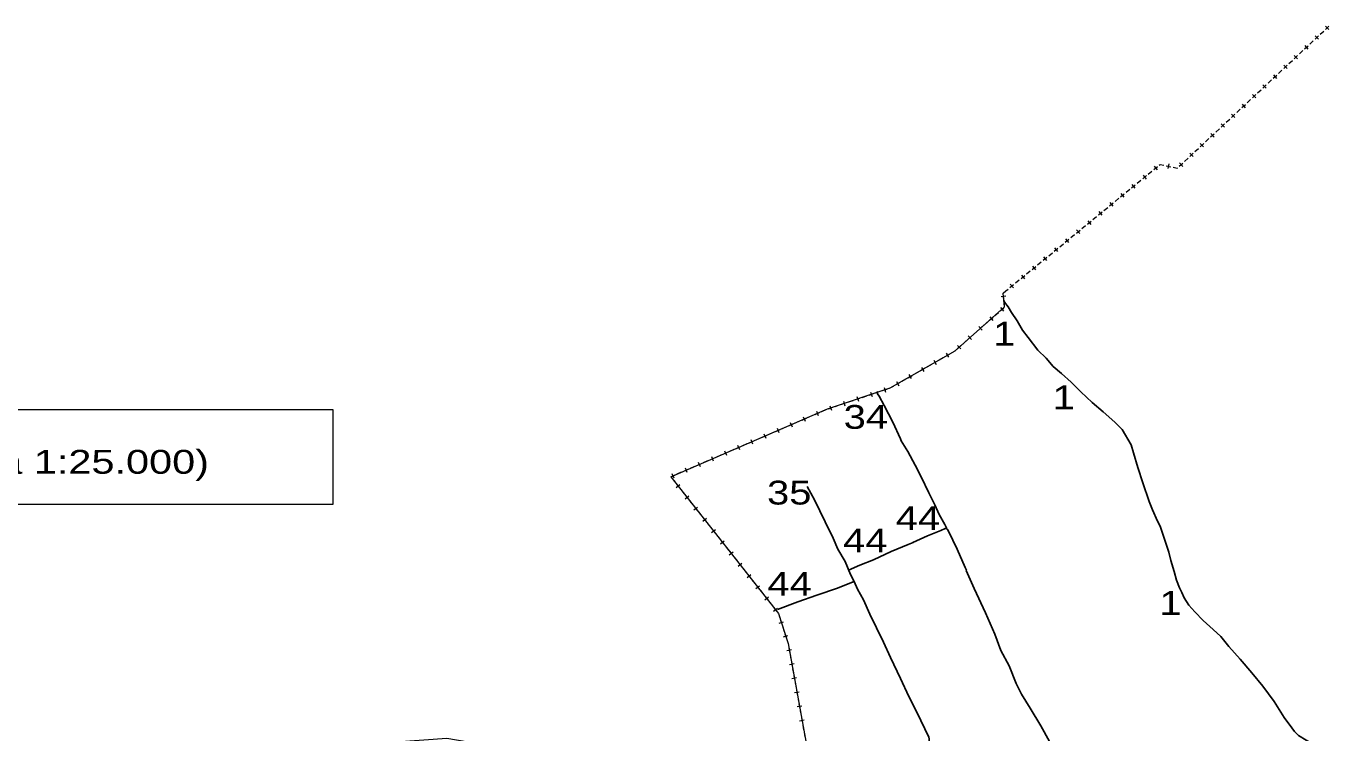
# Model space of a CAD drawing. Extents: x 476989 to 498418, y 4381813 to 4416555.
# Drawn here: x 483391 to 486122, y 4387830 to 4389313 of the extents above; entities that cross this region are included whole.
import ezdxf
from ezdxf.enums import TextEntityAlignment as Align

# ---------------------------------------------------------------- set-up
doc = ezdxf.new("R2010")
doc.units = 0
doc.header["$LTSCALE"] = 20
for name, color, linetype, lineweight in [('13', 7, 'Continuous', 13), ('34', 7, 'Continuous', 13), ('6', 7, 'Continuous', 25)]:
    doc.layers.add(name, color=color, linetype=linetype, lineweight=lineweight)

msp = doc.modelspace()

# ---------------------------------------------------------------- linework, layer by layer
at = {"layer": '13'}
msp.add_lwpolyline([(480316.85, 4388508.69), (484033.85, 4388508.69), (484033.85, 4388309.52), (480316.85, 4388309.52)], close=True, dxfattribs=at)
at = {"layer": '34'}
for p, q in [((486103.63, 4389295.79), (486110.92, 4389302.62)), ((486114.56, 4389306.04), (486121.86, 4389312.87)), ((486114.79, 4389313.1), (486121.63, 4389305.81)), ((486081.74, 4389275.28), (486089.04, 4389282.12)), ((486092.68, 4389285.53), (486099.98, 4389292.37)), ((486092.91, 4389292.6), (486099.75, 4389285.3)), ((486048.91, 4389244.52), (486056.21, 4389251.35)), ((486049.14, 4389251.58), (486055.98, 4389244.29)), ((486059.86, 4389254.77), (486067.16, 4389261.61)), ((486070.8, 4389265.02), (486078.09, 4389271.86)), ((486071.03, 4389272.09), (486077.86, 4389264.79)), ((486016.09, 4389213.76), (486023.39, 4389220.6)), ((486027.03, 4389224.01), (486034.33, 4389230.85)), ((486027.26, 4389231.08), (486034.1, 4389223.78)), ((486037.98, 4389234.27), (486045.27, 4389241.1)), ((485994.21, 4389193.25), (486001.51, 4389200.09)), ((486005.15, 4389203.5), (486012.45, 4389210.34)), ((486005.38, 4389210.57), (486012.22, 4389203.27)), ((485961.38, 4389162.49), (485968.68, 4389169.33)), ((485961.61, 4389169.55), (485968.45, 4389162.26)), ((485972.33, 4389172.74), (485979.62, 4389179.58)), ((485983.27, 4389182.99), (485990.56, 4389189.83)), ((485983.5, 4389190.06), (485990.33, 4389182.77)), ((485928.56, 4389131.73), (485935.86, 4389138.57)), ((485939.5, 4389141.98), (485946.8, 4389148.82)), ((485939.73, 4389149.05), (485946.57, 4389141.75)), ((485950.45, 4389152.24), (485957.74, 4389159.08)), ((485906.68, 4389111.22), (485913.98, 4389118.06)), ((485917.62, 4389121.47), (485924.91, 4389128.31)), ((485917.85, 4389128.54), (485924.68, 4389121.24)), ((485873.85, 4389080.46), (485881.15, 4389087.3)), ((485874.08, 4389087.53), (485880.92, 4389080.23)), ((485884.8, 4389090.72), (485892.09, 4389097.55)), ((485895.73, 4389100.97), (485903.03, 4389107.8)), ((485895.96, 4389108.03), (485902.8, 4389100.74)), ((485841.03, 4389049.7), (485848.33, 4389056.54)), ((485851.97, 4389059.95), (485859.27, 4389066.79)), ((485852.2, 4389067.02), (485859.04, 4389059.72)), ((485862.91, 4389070.21), (485870.21, 4389077.05)), ((485819.15, 4389029.2), (485826.44, 4389036.03)), ((485830.09, 4389039.45), (485837.38, 4389046.28)), ((485830.31, 4389046.51), (485837.15, 4389039.22)), ((485743.01, 4389002.49), (485750.74, 4389008.83)), ((485754.59, 4389012), (485762.32, 4389018.34)), ((485755.29, 4389019.04), (485761.63, 4389011.31)), ((485780.35, 4389020.26), (485790.11, 4389018.09)), ((485786.31, 4389024.05), (485784.14, 4389014.29)), ((485808.2, 4389018.94), (485815.5, 4389025.78)), ((485808.43, 4389026.01), (485815.27, 4389018.71)), ((485708.23, 4388973.95), (485715.96, 4388980.29)), ((485708.92, 4388980.98), (485715.27, 4388973.25)), ((485719.82, 4388983.46), (485727.55, 4388989.81)), ((485731.41, 4388992.97), (485739.14, 4388999.32)), ((485732.1, 4389000.01), (485738.45, 4388992.28)), ((485673.46, 4388945.41), (485681.19, 4388951.76)), ((485685.05, 4388954.92), (485692.78, 4388961.27)), ((485685.74, 4388961.96), (485692.08, 4388954.23)), ((485696.64, 4388964.44), (485704.37, 4388970.78)), ((485638.68, 4388916.87), (485646.41, 4388923.22)), ((485639.37, 4388923.91), (485645.72, 4388916.18)), ((485650.28, 4388926.39), (485658.01, 4388932.73)), ((485661.86, 4388935.9), (485669.59, 4388942.24)), ((485662.56, 4388942.93), (485668.9, 4388935.2)), ((485603.91, 4388888.34), (485611.64, 4388894.68)), ((485615.5, 4388897.85), (485623.23, 4388904.19)), ((485616.19, 4388904.88), (485622.54, 4388897.15)), ((485627.09, 4388907.36), (485634.82, 4388913.71)), ((485569.13, 4388859.8), (485576.86, 4388866.14)), ((485569.83, 4388866.83), (485576.17, 4388859.1)), ((485580.73, 4388869.31), (485588.46, 4388875.66)), ((485592.32, 4388878.82), (485600.05, 4388885.16)), ((485593.01, 4388885.86), (485599.35, 4388878.13)), ((485534.36, 4388831.26), (485542.09, 4388837.6)), ((485545.95, 4388840.77), (485553.68, 4388847.11)), ((485546.64, 4388847.81), (485552.99, 4388840.08)), ((485557.55, 4388850.29), (485565.28, 4388856.63)), ((485499.58, 4388802.72), (485507.31, 4388809.06)), ((485500.28, 4388809.76), (485506.62, 4388802.03)), ((485511.18, 4388812.24), (485518.91, 4388818.58)), ((485522.77, 4388821.75), (485530.5, 4388828.09)), ((485523.46, 4388828.78), (485529.8, 4388821.05)), ((485476.4, 4388783.69), (485484.13, 4388790.04)), ((485477.09, 4388790.73), (485483.44, 4388783)), ((485488, 4388793.21), (485495.73, 4388799.55)), ((485441.63, 4388755.16), (485444.8, 4388757.76)), ((485444.8, 4388757.76), (485449.36, 4388761.5)), ((485453.22, 4388764.67), (485460.95, 4388771.01)), ((485453.91, 4388771.71), (485460.26, 4388763.98)), ((485464.81, 4388774.19), (485472.54, 4388780.53)), ((485434.71, 4388745.92), (485444.65, 4388746.95)), ((485440.19, 4388741.47), (485439.16, 4388751.41)), ((485441.74, 4388726.56), (485440.71, 4388736.5)), ((485410.23, 4388695.89), (485417.72, 4388702.52)), ((485410.66, 4388702.95), (485417.28, 4388695.46)), ((485421.46, 4388705.83), (485428.95, 4388712.46)), ((485432.69, 4388715.76), (485440.18, 4388722.39)), ((485433.12, 4388722.82), (485439.75, 4388715.33)), ((485376.54, 4388666.09), (485384.03, 4388672.72)), ((485387.76, 4388676.02), (485395.25, 4388682.65)), ((485388.2, 4388683.08), (485394.82, 4388675.59)), ((485399, 4388685.96), (485406.49, 4388692.59)), ((485354.07, 4388646.22), (485361.56, 4388652.85)), ((485365.3, 4388656.15), (485372.79, 4388662.78)), ((485365.73, 4388663.21), (485372.36, 4388655.72)), ((485304.59, 4388612.84), (485313.26, 4388617.81)), ((485317.59, 4388620.29), (485326.26, 4388625.27)), ((485319.44, 4388627.12), (485324.41, 4388618.44)), ((485342.84, 4388636.28), (485350.33, 4388642.91)), ((485343.27, 4388643.34), (485349.9, 4388635.85)), ((485265.56, 4388590.45), (485274.23, 4388595.43)), ((485267.41, 4388597.28), (485272.38, 4388588.6)), ((485278.57, 4388597.92), (485287.25, 4388602.89)), ((485291.58, 4388605.37), (485300.25, 4388610.35)), ((485293.42, 4388612.2), (485298.4, 4388603.52)), ((485213.53, 4388560.61), (485222.2, 4388565.59)), ((485215.38, 4388567.44), (485220.35, 4388558.76)), ((485226.54, 4388568.08), (485235.22, 4388573.05)), ((485239.54, 4388575.53), (485248.22, 4388580.51)), ((485241.39, 4388582.36), (485246.37, 4388573.68)), ((485252.56, 4388583), (485261.23, 4388587.97)), ((485132.46, 4388535.92), (485135.64, 4388526.44)), ((485143.53, 4388534.36), (485153.01, 4388537.55)), ((485157.74, 4388539.13), (485167.22, 4388542.32)), ((485160.89, 4388545.47), (485164.07, 4388535.99)), ((485171.96, 4388543.91), (485181.44, 4388547.09)), ((485186.17, 4388548.68), (485195.65, 4388551.87)), ((485189.32, 4388555.02), (485192.5, 4388545.54)), ((485058.65, 4388504.67), (485067.83, 4388508.63)), ((485072.45, 4388510.49), (485081.93, 4388513.67)), ((485075.6, 4388516.82), (485078.79, 4388507.34)), ((485086.67, 4388515.26), (485096.15, 4388518.45)), ((485100.88, 4388520.04), (485110.36, 4388523.22)), ((485104.03, 4388526.37), (485107.21, 4388516.89)), ((485115.1, 4388524.81), (485124.58, 4388528)), ((485129.31, 4388529.59), (485138.79, 4388532.77)), ((484992.41, 4388481.53), (484996.38, 4388472.35)), ((485003.58, 4388480.9), (485012.76, 4388484.86)), ((485017.34, 4388486.84), (485026.52, 4388490.8)), ((485019.95, 4388493.41), (485023.91, 4388484.23)), ((485031.11, 4388492.78), (485040.29, 4388496.75)), ((485044.87, 4388498.72), (485054.05, 4388502.69)), ((485047.48, 4388505.3), (485051.45, 4388496.11)), ((484934.73, 4388451.19), (484943.92, 4388455.15)), ((484937.34, 4388457.76), (484941.31, 4388448.58)), ((484948.51, 4388457.13), (484957.69, 4388461.09)), ((484962.27, 4388463.07), (484971.45, 4388467.03)), ((484964.88, 4388469.64), (484968.84, 4388460.46)), ((484976.04, 4388469.01), (484985.22, 4388472.98)), ((484989.8, 4388474.95), (484998.99, 4388478.92)), ((484879.66, 4388427.42), (484888.85, 4388431.38)), ((484882.27, 4388433.99), (484886.24, 4388424.81)), ((484893.44, 4388433.36), (484902.62, 4388437.32)), ((484907.2, 4388439.3), (484916.38, 4388443.26)), ((484909.81, 4388445.87), (484913.77, 4388436.69)), ((484920.97, 4388445.25), (484930.15, 4388449.21)), ((484810.83, 4388397.71), (484820.01, 4388401.67)), ((484824.6, 4388403.65), (484833.78, 4388407.61)), ((484827.2, 4388410.22), (484831.17, 4388401.04)), ((484838.37, 4388409.59), (484847.55, 4388413.56)), ((484852.13, 4388415.53), (484861.31, 4388419.5)), ((484854.74, 4388422.11), (484858.7, 4388412.92)), ((484865.9, 4388421.48), (484875.08, 4388425.44)), ((484744.6, 4388374.57), (484748.56, 4388365.39)), ((484755.76, 4388373.94), (484764.94, 4388377.9)), ((484769.53, 4388379.88), (484778.71, 4388383.84)), ((484772.13, 4388386.45), (484776.1, 4388377.27)), ((484783.3, 4388385.82), (484792.48, 4388389.79)), ((484797.06, 4388391.76), (484806.24, 4388395.73)), ((484799.67, 4388398.34), (484803.63, 4388389.16)), ((484742, 4388368), (484751.17, 4388371.96)), ((484745.09, 4388364.07), (484751.28, 4388356.22)), ((484753.54, 4388345.27), (484761.39, 4388351.45)), ((484754.37, 4388352.29), (484760.56, 4388344.43)), ((484763.65, 4388340.5), (484769.84, 4388332.65)), ((484772.1, 4388321.7), (484779.95, 4388327.88)), ((484772.93, 4388328.72), (484779.12, 4388320.86)), ((484782.21, 4388316.93), (484788.4, 4388309.08)), ((484790.66, 4388298.13), (484798.52, 4388304.31)), ((484791.49, 4388305.15), (484797.68, 4388297.29)), ((484800.77, 4388293.36), (484806.96, 4388285.51)), ((484809.22, 4388274.56), (484817.08, 4388280.74)), ((484810.05, 4388281.58), (484816.24, 4388273.72)), ((484819.33, 4388269.79), (484825.52, 4388261.94)), ((484827.78, 4388250.99), (484835.64, 4388257.17)), ((484828.61, 4388258.01), (484834.8, 4388250.15)), ((484837.89, 4388246.22), (484844.08, 4388238.37)), ((484846.34, 4388227.42), (484854.2, 4388233.6)), ((484847.17, 4388234.44), (484853.36, 4388226.58)), ((484856.45, 4388222.65), (484862.64, 4388214.8)), ((484864.9, 4388203.85), (484872.76, 4388210.03)), ((484865.73, 4388210.87), (484871.92, 4388203.01)), ((484875.01, 4388199.08), (484881.2, 4388191.23)), ((484883.46, 4388180.28), (484891.32, 4388186.46)), ((484884.29, 4388187.3), (484890.48, 4388179.44)), ((484893.57, 4388175.52), (484899.76, 4388167.66)), ((484902.02, 4388156.71), (484909.88, 4388162.9)), ((484902.85, 4388163.73), (484909.04, 4388155.87)), ((484912.13, 4388151.95), (484918.32, 4388144.09)), ((484920.58, 4388133.14), (484928.44, 4388139.33)), ((484921.41, 4388140.16), (484927.6, 4388132.3)), ((484930.69, 4388128.38), (484936.88, 4388120.52)), ((484939.14, 4388109.57), (484947, 4388115.76)), ((484939.97, 4388116.59), (484946.16, 4388108.73)), ((484949.25, 4388104.81), (484955.44, 4388096.95)), ((484957.7, 4388086), (484965.56, 4388092.19)), ((484958.53, 4388093.02), (484964.72, 4388085.16)), ((484969.19, 4388060.71), (484978.73, 4388063.74)), ((484972.45, 4388066.99), (484975.47, 4388057.46)), ((484976.99, 4388052.69), (484980.01, 4388043.16)), ((484978.27, 4388032.12), (484987.8, 4388035.14)), ((484981.52, 4388038.4), (484984.55, 4388028.87)), ((484985.5, 4388003.73), (484995.34, 4388005.51)), ((484989.53, 4388009.54), (484991.31, 4387999.7)), ((484992.2, 4387994.78), (484993.99, 4387984.94)), ((484990.85, 4387974.21), (485000.69, 4387975.99)), ((484994.88, 4387980.02), (484996.66, 4387970.18)), ((484997.55, 4387965.26), (484999.33, 4387955.42)), ((484996.19, 4387944.69), (485006.03, 4387946.47)), ((485000.22, 4387950.5), (485002, 4387940.66)), ((485002.89, 4387935.74), (485004.67, 4387925.9)), ((485001.54, 4387915.17), (485011.38, 4387916.95)), ((485005.56, 4387920.98), (485007.35, 4387911.14)), ((485006.88, 4387885.65), (485016.72, 4387887.43)), ((485008.24, 4387906.22), (485010.02, 4387896.38)), ((485010.91, 4387891.46), (485012.69, 4387881.62)), ((485012.22, 4387856.13), (485022.06, 4387857.91)), ((485013.58, 4387876.7), (485015.36, 4387866.86)), ((485016.25, 4387861.94), (485018.03, 4387852.1)), ((485018.92, 4387847.18), (485020.71, 4387837.34)), ((485021.6, 4387832.42), (485023.38, 4387822.58))]:
    msp.add_line(p, q, dxfattribs=at)
for points in [[(485766.19, 4389021.51), (485768, 4389023), (485775.48, 4389021.34)], [(485794.99, 4389017), (485804, 4389015), (485804.56, 4389015.53)], [(484742, 4388368), (485071, 4388510), (485202, 4388554), (485338, 4388632), (485442, 4388724), (485439, 4388753), (485444.8, 4388757.76)], [(485330.6, 4388627.76), (485338, 4388632), (485339.1, 4388632.98)], [(485200.39, 4388553.46), (485202, 4388554), (485209.2, 4388558.13)], [(484742, 4388368), (484968, 4388081), (484988, 4388018), (485030, 4387786), (485030, 4387747), (484843, 4387760), (484712, 4387762), (484623, 4387793), (484342, 4387807), (484273, 4387819), (484108.44, 4387807.03)], [(484967.81, 4388081.24), (484968, 4388081), (484970.93, 4388071.76)], [(484986.06, 4388024.1), (484988, 4388018), (484988.64, 4388014.46)]]:
    msp.add_lwpolyline(points, dxfattribs=at)
at = {"layer": '6'}
for points in [[(485440.7, 4388737.5), (485441.99, 4388734.08), (485449.36, 4388724.07), (485456.08, 4388712.46), (485468.1, 4388694.6), (485479.36, 4388675.04), (485491.14, 4388660.05), (485511.34, 4388633.52), (485528.76, 4388616.39), (485543.57, 4388599.11), (485561.47, 4388584.67), (485581.34, 4388566.46), (485601.43, 4388546.21), (485625.33, 4388523.43), (485648.4, 4388503.95), (485672.73, 4388482.48), (485688.17, 4388467.01), (485707.06, 4388435), (485712.35, 4388418.05), (485721.25, 4388387.26), (485731.78, 4388354.89), (485744.85, 4388316.19), (485751.85, 4388298.7), (485762.78, 4388274.7), (485768, 4388263.85), (485779.02, 4388230.66), (485785.91, 4388209.4), (485790.76, 4388192.02), (485797.49, 4388169.1), (485801.96, 4388151.04), (485808.65, 4388135.09), (485813.43, 4388124.82), (485818.42, 4388114.08), (485828.47, 4388098.7), (485840.76, 4388084.25), (485858.12, 4388066.2), (485879.3, 4388047.48), (485895.16, 4388032.58), (485911.89, 4388012.02)], [(485224.04, 4388447.11), (485207.78, 4388482.2), (485189.48, 4388517.58), (485178.95, 4388536.92), (485175.21, 4388541.77), (485174.76, 4388545.72), (485175.43, 4388546.79)], [(485228.46, 4388437.56), (485225.43, 4388443.22), (485224.04, 4388447.11)], [(485228.44, 4388437.61), (485239.13, 4388420.45), (485254.49, 4388392.02), (485266.8, 4388367.49), (485283.36, 4388333.76), (485295.91, 4388308.62), (485304.83, 4388288.39), (485316.35, 4388267.98), (485320.79, 4388259.19)], [(485028.24, 4388347.65), (485043.19, 4388319.65), (485065.47, 4388273.4), (485082.48, 4388238.78), (485092.64, 4388215.91), (485107.46, 4388190.21), (485118.68, 4388162.55), (485126.48, 4388148.04)], [(485249.87, 4388230.09), (485280.42, 4388243.58), (485308.34, 4388255.24), (485317.7, 4388259.03), (485319.71, 4388259.39), (485321.11, 4388258.63), (485322.2, 4388257.5), (485324.66, 4388253.42), (485342.55, 4388215.99), (485359.1, 4388177.28), (485361.75, 4388171.57)], [(485114.58, 4388171.97), (485138.19, 4388182.42), (485167.22, 4388193.28), (485204.15, 4388210.77), (485239.57, 4388225.59), (485250.04, 4388230.2)], [(485361.68, 4388171.46), (485378.46, 4388133.46), (485401.8, 4388082.2), (485421.34, 4388037.69), (485434.11, 4388003.69), (485451.8, 4387971.36), (485466.24, 4387934.48), (485477.35, 4387911.58), (485495.47, 4387882.54), (485517.79, 4387845.13), (485536.33, 4387812.23), (485553.28, 4387782.16)], [(484965.74, 4388089.59), (485008.16, 4388105.83), (485048.14, 4388119.54), (485091.39, 4388133.96), (485124.78, 4388147.26), (485126.61, 4388148.09)], [(485126.61, 4388148.09), (485133.89, 4388132.19), (485146.45, 4388109.63), (485159.7, 4388079.42), (485173.4, 4388051.16), (485187.78, 4388020.66), (485202.68, 4387988.5), (485223.68, 4387944.5), (485241.45, 4387906.87), (485258.16, 4387874.34), (485274.72, 4387839.19), (485283.44, 4387821.96), (485283.82, 4387817.85), (485284.05, 4387813.43), (485283.91, 4387808.34), (485279.89, 4387789.2)], [(485912.17, 4388011.78), (485935.61, 4387985.33), (485960.06, 4387956.84), (485983.16, 4387928.35), (486007.28, 4387896.47), (486027.88, 4387862.88), (486044.27, 4387841.38), (486049.75, 4387833.89), (486058.02, 4387825.05), (486074.09, 4387815.1), (486088.73, 4387807.17), (486116.23, 4387792.4)]]:
    msp.add_lwpolyline(points, dxfattribs=at)

# ---------------------------------------------------------------- texts
at = {"layer": '13'}
for s, width, p in [('34', 1.25, (485151.06, 4388468.36)), ('6.2.4. Mapa dels camins que formen part de rutes excursionistes. (Escala 1:25.000)', 1.3, (482162.88, 4388374.15)), ('35', 1.25, (484990.5, 4388309.57)), ('44', 1.25, (485260.34, 4388256.07)), ('44', 1.25, (485149.96, 4388209.26)), ('44', 1.25, (484991.33, 4388118.37))]:
    msp.add_text(s, height=50, dxfattribs=dict(at, width=width)).set_placement(p, align=Align.CENTER)
at = {"layer": '6', "width": 1.25}
for p in [(485441.14, 4388643), (485565.93, 4388509.28), (485789.69, 4388078.22)]:
    msp.add_text('1', height=50, dxfattribs=at).set_placement(p, align=Align.CENTER)

doc.saveas('drawing.dxf')
